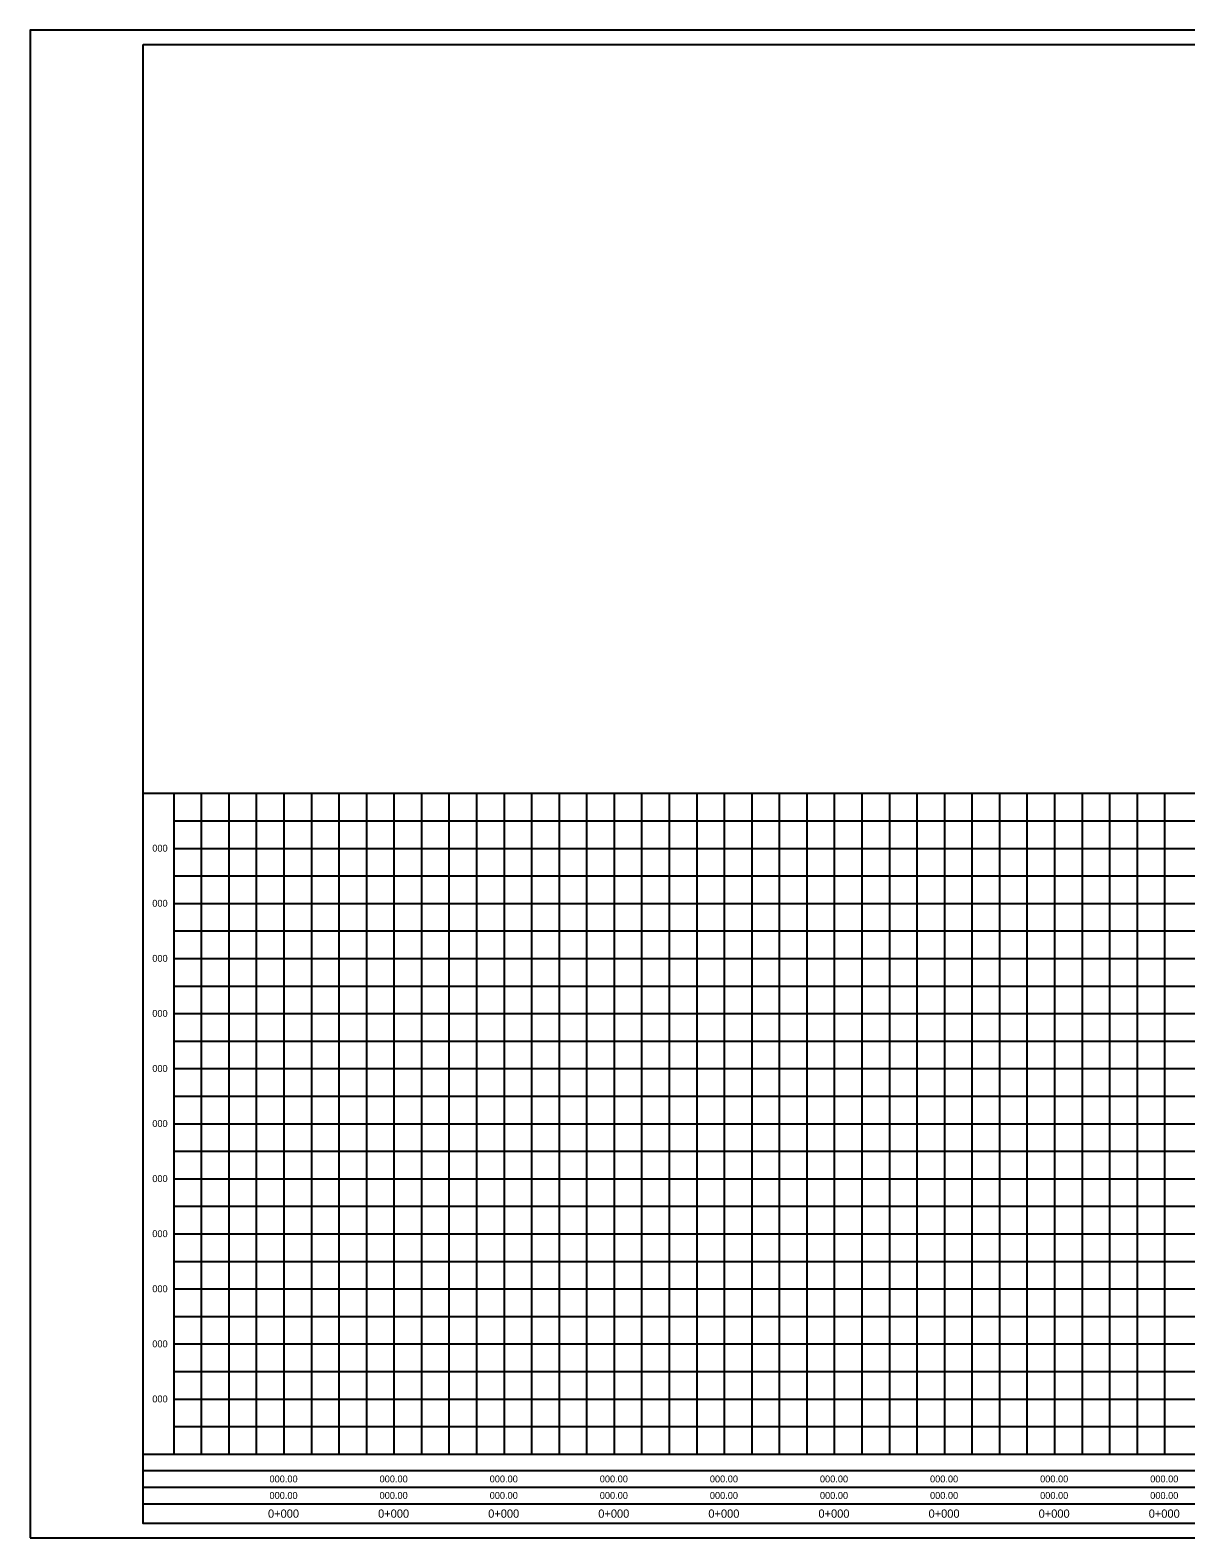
# Model space of a CAD drawing. Extents: x 613360 to 613780, y 4825621 to 4825911.
# Drawn here: x 613359.6 to 613569.5, y 4825620.9 to 4825894.7 of the extents above; entities that cross this region are included whole.
import ezdxf

# ---------------------------------------------------------------- set-up
doc = ezdxf.new("R2010")
doc.units = 0
for name, color, linetype in [('G-ANNO-TEXT', 7, 'Continuous'), ('G-GRID-MAJ', 7, 'Continuous'), ('G-GRID-MIN', 7, 'Continuous'), ('G-TTLB-OTLN', 7, 'Continuous'), ('G-TTLB-OTLN-PB', 7, 'Continuous')]:
    doc.layers.add(name, color=color, linetype=linetype)

msp = doc.modelspace()

# ---------------------------------------------------------------- linework, layer by layer
at = {"layer": 'G-GRID-MAJ'}
for p, q in [((613385.73, 4825636.11), (613385.73, 4825756.11)), ((613405.73, 4825636.11), (613405.73, 4825756.11)), ((613425.73, 4825636.11), (613425.73, 4825756.11)), ((613445.73, 4825636.11), (613445.73, 4825756.11)), ((613465.73, 4825636.11), (613465.73, 4825756.11)), ((613485.73, 4825636.11), (613485.73, 4825756.11)), ((613505.73, 4825636.11), (613505.73, 4825756.11)), ((613525.73, 4825636.11), (613525.73, 4825756.11)), ((613545.73, 4825636.11), (613545.73, 4825756.11)), ((613565.73, 4825636.11), (613565.73, 4825756.11)), ((613385.73, 4825746.11), (613705.73, 4825746.11)), ((613385.73, 4825736.11), (613705.73, 4825736.11)), ((613385.73, 4825726.11), (613705.73, 4825726.11)), ((613385.73, 4825716.11), (613705.73, 4825716.11)), ((613385.73, 4825706.11), (613705.73, 4825706.11)), ((613385.73, 4825696.11), (613705.73, 4825696.11)), ((613385.73, 4825686.11), (613705.73, 4825686.11)), ((613385.73, 4825676.11), (613705.73, 4825676.11)), ((613385.73, 4825666.11), (613705.73, 4825666.11)), ((613385.73, 4825656.11), (613705.73, 4825656.11)), ((613385.73, 4825646.11), (613705.73, 4825646.11))]:
    msp.add_line(p, q, dxfattribs=at)
at = {"layer": 'G-GRID-MIN'}
for p, q in [((613390.73, 4825636.11), (613390.73, 4825756.11)), ((613395.73, 4825636.11), (613395.73, 4825756.11)), ((613400.73, 4825636.11), (613400.73, 4825756.11)), ((613410.73, 4825636.11), (613410.73, 4825756.11)), ((613415.73, 4825636.11), (613415.73, 4825756.11)), ((613420.73, 4825636.11), (613420.73, 4825756.11)), ((613430.73, 4825636.11), (613430.73, 4825756.11)), ((613435.73, 4825636.11), (613435.73, 4825756.11)), ((613440.73, 4825636.11), (613440.73, 4825756.11)), ((613450.73, 4825636.11), (613450.73, 4825756.11)), ((613455.73, 4825636.11), (613455.73, 4825756.11)), ((613460.73, 4825636.11), (613460.73, 4825756.11)), ((613470.73, 4825636.11), (613470.73, 4825756.11)), ((613475.73, 4825636.11), (613475.73, 4825756.11)), ((613480.73, 4825636.11), (613480.73, 4825756.11)), ((613490.73, 4825636.11), (613490.73, 4825756.11)), ((613495.73, 4825636.11), (613495.73, 4825756.11)), ((613500.73, 4825636.11), (613500.73, 4825756.11)), ((613510.73, 4825636.11), (613510.73, 4825756.11)), ((613515.73, 4825636.11), (613515.73, 4825756.11)), ((613520.73, 4825636.11), (613520.73, 4825756.11)), ((613530.73, 4825636.11), (613530.73, 4825756.11)), ((613535.73, 4825636.11), (613535.73, 4825756.11)), ((613540.73, 4825636.11), (613540.73, 4825756.11)), ((613550.73, 4825636.11), (613550.73, 4825756.11)), ((613555.73, 4825636.11), (613555.73, 4825756.11)), ((613560.73, 4825636.11), (613560.73, 4825756.11)), ((613385.73, 4825751.11), (613705.73, 4825751.11)), ((613385.73, 4825741.11), (613705.73, 4825741.11)), ((613385.73, 4825731.11), (613705.73, 4825731.11)), ((613385.73, 4825721.11), (613705.73, 4825721.11)), ((613385.73, 4825711.11), (613705.73, 4825711.11)), ((613385.73, 4825701.11), (613705.73, 4825701.11)), ((613385.73, 4825691.11), (613705.73, 4825691.11)), ((613385.73, 4825681.11), (613705.73, 4825681.11)), ((613385.73, 4825671.11), (613705.73, 4825671.11)), ((613385.73, 4825661.11), (613705.73, 4825661.11)), ((613385.73, 4825651.11), (613705.73, 4825651.11)), ((613385.73, 4825641.11), (613705.73, 4825641.11))]:
    msp.add_line(p, q, dxfattribs=at)
at = {"layer": 'G-TTLB-OTLN'}
for p, q in [((613380.09, 4825756.11), (613774.18, 4825756.11)), ((613380.09, 4825636.11), (613710.78, 4825636.11)), ((613380.09, 4825633.11), (613774.18, 4825633.11)), ((613380.09, 4825630.11), (613749.42, 4825630.11)), ((613380.09, 4825627.11), (613749.42, 4825627.11))]:
    msp.add_line(p, q, dxfattribs=at)
msp.add_lwpolyline([(613380.09, 4825892.08), (613774.18, 4825892.08), (613774.18, 4825623.51), (613380.09, 4825623.51)], close=True, dxfattribs=at)
at = {"layer": 'G-TTLB-OTLN-PB'}
for p, q in [((613364.58, 4825894.68), (613359.58, 4825894.68)), ((613359.58, 4825894.68), (613359.58, 4825888.68)), ((613359.58, 4825626.91), (613359.58, 4825620.91)), ((613359.58, 4825620.91), (613364.58, 4825620.91))]:
    msp.add_line(p, q, dxfattribs=at)
msp.add_lwpolyline([(613359.58, 4825620.91), (613780.27, 4825620.91), (613780.27, 4825894.68), (613359.58, 4825894.68)], close=True, dxfattribs=at)

# ---------------------------------------------------------------- texts
at = {"layer": 'G-ANNO-TEXT'}
for p in [(613381.77, 4825745.51), (613381.77, 4825735.51), (613381.77, 4825725.51), (613381.77, 4825715.51), (613381.77, 4825695.51), (613381.77, 4825685.51), (613381.77, 4825675.51), (613381.77, 4825665.51), (613381.77, 4825655.51), (613381.77, 4825645.51)]:
    msp.add_text('000', height=1.25, rotation=360, dxfattribs=at).set_placement(p)
for s, height, p in [('000', 1.25, (613381.77, 4825705.51)), ('000.00', 1.25, (613403.06, 4825630.98)), ('000.00', 1.25, (613423.06, 4825630.98)), ('000.00', 1.25, (613443.06, 4825630.98)), ('000.00', 1.25, (613463.06, 4825630.98)), ('000.00', 1.25, (613483.06, 4825630.98)), ('000.00', 1.25, (613503.06, 4825630.98)), ('000.00', 1.25, (613523.06, 4825630.98)), ('000.00', 1.25, (613543.06, 4825630.98)), ('000.00', 1.25, (613563.06, 4825630.98)), ('000.00', 1.25, (613403.06, 4825627.98)), ('000.00', 1.25, (613423.06, 4825627.98)), ('000.00', 1.25, (613443.06, 4825627.98)), ('000.00', 1.25, (613463.06, 4825627.98)), ('000.00', 1.25, (613483.06, 4825627.98)), ('000.00', 1.25, (613503.06, 4825627.98)), ('000.00', 1.25, (613523.06, 4825627.98)), ('000.00', 1.25, (613543.06, 4825627.98)), ('000.00', 1.25, (613563.06, 4825627.98)), ('0+000', 1.5, (613402.79, 4825624.56)), ('0+000', 1.5, (613422.79, 4825624.56)), ('0+000', 1.5, (613442.79, 4825624.56)), ('0+000', 1.5, (613462.79, 4825624.56)), ('0+000', 1.5, (613482.79, 4825624.56)), ('0+000', 1.5, (613502.79, 4825624.56)), ('0+000', 1.5, (613522.79, 4825624.56)), ('0+000', 1.5, (613542.79, 4825624.56)), ('0+000', 1.5, (613562.79, 4825624.56))]:
    msp.add_text(s, height=height, dxfattribs=at).set_placement(p)

doc.saveas('drawing.dxf')
